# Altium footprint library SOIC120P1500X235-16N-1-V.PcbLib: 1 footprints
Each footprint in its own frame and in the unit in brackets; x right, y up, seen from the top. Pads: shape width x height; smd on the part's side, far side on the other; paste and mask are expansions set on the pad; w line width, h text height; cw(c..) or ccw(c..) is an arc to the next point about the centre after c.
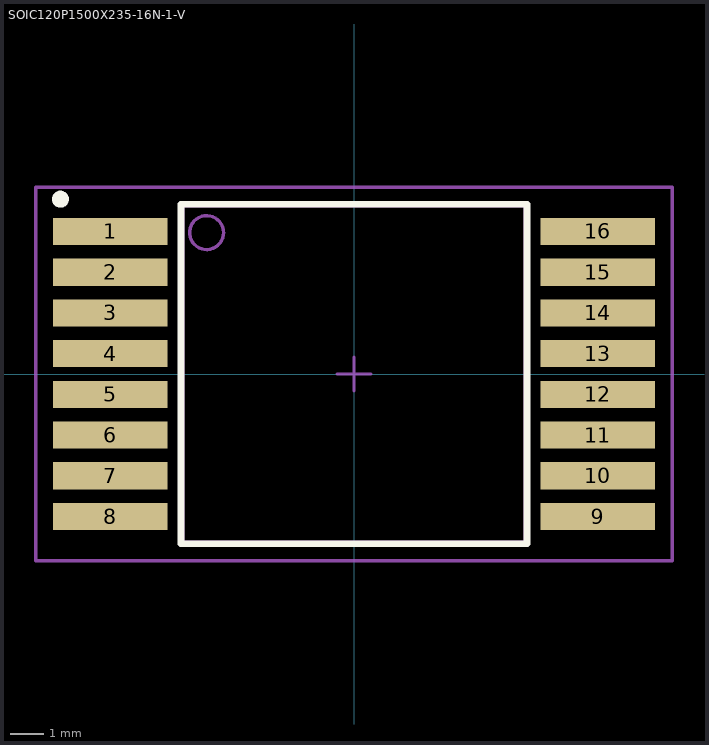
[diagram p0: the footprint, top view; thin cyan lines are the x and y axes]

## SOIC120P1500X235-16N-1-V [mm] "SOIC,1.20mm pitch;16 pin,10.15mm W X 9.90mm L X 2.35mm H body"
height 2.35
pads (16):
  rect 3.375x0.8 smd paste+0 mask+0: 1(-7.187,4.2) 2(-7.187,3) 3(-7.187,1.8) 4(-7.187,0.6) 5(-7.187,-0.6) 6(-7.187,-1.8) 7(-7.187,-3) 8(-7.187,-4.2) 9(7.187,-4.2) 10(7.187,-3) 11(7.187,-1.8) 12(7.187,-0.6) 13(7.187,0.6) 14(7.187,1.8) 15(7.187,3) 16(7.187,4.2)
Top Overlay:
  circle w0.25: c-8.65,5.15 r0.125
  lines w0.2: -5.1,-5 5.1,-5 5.1,5 -5.1,5 -5.1,-5
M3 (ASY_Text_Top):
  text ".DESIGNATOR" at 0,0 h1.2
M13 (CMP_Body_OTL_Top):
  circle w0.1: c-4.343,4.166 r0.5
  lines w0.1: -5.05,-4.95 5.05,-4.95 5.05,4.95 -5.05,4.95 -5.05,-4.95
M15 (CMP_Courtyard_Top):
  lines w0.1: -0.5,0 0.5,0 ; 0,-0.5 0,0.5 ; -9.375,-5.5 -9.375,5.5 9.375,5.5 9.375,-5.5 -9.375,-5.5
3D body "PG-HDSOP-16-1_Z8B00189145_V01_3D.stp": height 2.2, standoff -0.16, extent -7.5,-4.95 7.5,4.95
